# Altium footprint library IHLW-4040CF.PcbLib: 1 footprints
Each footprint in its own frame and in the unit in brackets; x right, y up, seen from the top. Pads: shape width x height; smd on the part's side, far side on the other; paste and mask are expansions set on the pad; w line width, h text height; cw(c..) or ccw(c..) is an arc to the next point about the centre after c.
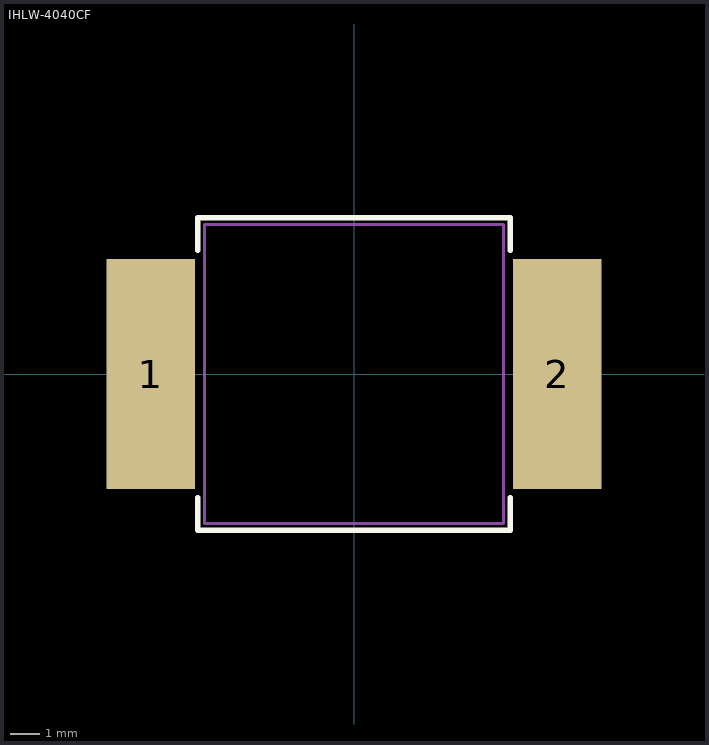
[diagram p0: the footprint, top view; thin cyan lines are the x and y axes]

## IHLW-4040CF [mm] "Vishay Dale IHLW data sheet"
height 3.8
pads (2):
  rect 3x7.8 smd: 1(-6.9,0) 2(6.9,0)
Top Overlay:
  lines w0.178: -5.3,-4.2 -5.3,-5.3 0,-5.3 5.3,-5.3 5.3,-4.2 ; -5.3,4.2 -5.3,5.3 0,5.3 5.3,5.3 5.3,4.2
M5 Assembly Top:
  lines w0.102: -5.08,-5.08 5.08,-5.08 5.08,5.08 -5.08,5.08 -5.08,-2.286 -5.08,-5.08
  text ".Designator" at -1.75,-0.525 h1.02
3D body: height 3.8, standoff -2.4, extent -5.1,-5.149 5.1,5.149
